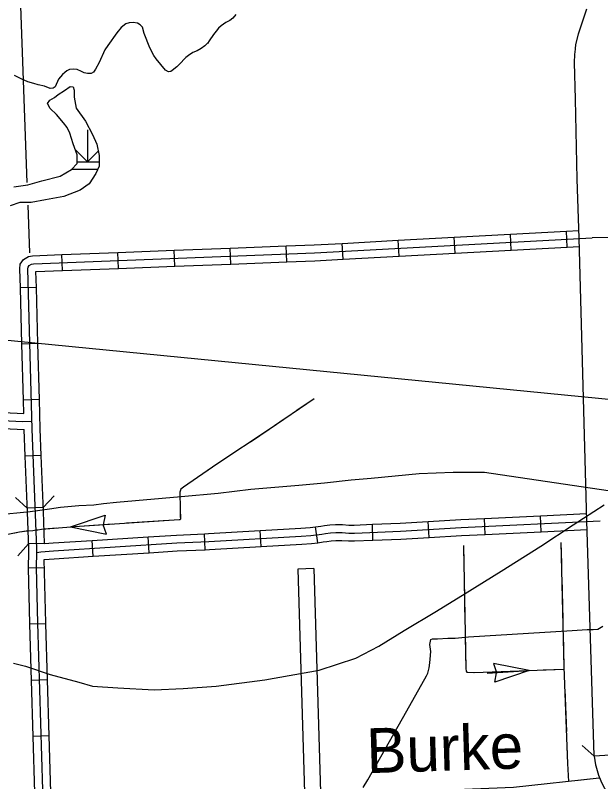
# Model space of a CAD drawing. Extents: x 1164457 to 1439835, y 1590918 to 1773502.
# Drawn here: x 1250237 to 1255743, y 1633937 to 1641151 of the extents above; entities that cross this region are included whole.
import ezdxf

# ---------------------------------------------------------------- set-up
doc = ezdxf.new("R2010")
doc.units = 0
for name, color, linetype in [('Level 10', 7, 'Continuous'), ('Level 32', 7, 'Continuous'), ('Level 35', 7, 'Continuous'), ('Level 37', 7, 'Continuous'), ('Level 38', 7, 'Continuous'), ('Level 43', 7, 'Continuous'), ('Level 44', 7, 'Continuous'), ('Level 45', 7, 'Continuous'), ('Level 46', 7, 'Continuous'), ('Level 47', 7, 'Continuous'), ('Level 5', 7, 'Continuous'), ('R_Draft', 7, 'Continuous')]:
    doc.layers.add(name, color=color, linetype=linetype)

msp = doc.modelspace()

# ---------------------------------------------------------------- linework, layer by layer
at = {"layer": 'Level 10'}
for points in [[(1255932.7, 1634192.4), (1255683.2, 1634177.2), (1255682.9, 1634182.2), (1255613.1, 1636387.6), (1255539.9, 1639052.5), (1255522.9, 1639608.2), (1255507.2, 1640362.9), (1255498.4, 1640706.4), (1255500.4, 1640783), (1255507.4, 1640833.5), (1255507.7, 1640838.1), (1255508.6, 1640872), (1255534.7, 1640977), (1255612.6, 1641210.8)], [(1255683.2, 1634177.2), (1255694, 1634093.9), (1255696.9, 1634084.6), (1255702.6, 1634062.8), (1255722, 1633998.8), (1255745.7, 1633943.1), (1255765.1, 1633903.6), (1255794.6, 1633848.4), (1255830.8, 1633799.8), (1255902, 1633727.8)]]:
    msp.add_lwpolyline(points, dxfattribs=at)
at = {"layer": 'Level 32'}
for p, q in [((1254901.8, 1638939.8), (1254893.7, 1639089.6)), ((1255429, 1638968.3), (1255421, 1639118)), ((1253847.3, 1638882.9), (1253839.3, 1639032.6)), ((1254374.6, 1638911.3), (1254366.5, 1639061.1)), ((1252263.9, 1638809.5), (1252258.2, 1638959.4)), ((1252791.6, 1638829.9), (1252785.8, 1638979.8)), ((1253320.1, 1638854.4), (1253312, 1639004.2)), ((1250681.1, 1638748.3), (1250675.3, 1638898.2)), ((1251208.7, 1638768.7), (1251202.9, 1638918.6)), ((1251736.3, 1638789.1), (1251730.5, 1638939)), ((1250435, 1638588.5), (1250285.1, 1638584.4)), ((1250449.3, 1638060.7), (1250299.4, 1638056.6)), ((1250463.6, 1637532.9), (1250313.7, 1637528.8)), ((1250480.8, 1637006), (1250330.9, 1637000.2)), ((1250499.6, 1636517.2), (1250349.7, 1636511.4)), ((1255184.2, 1636289.9), (1255177, 1636439.7)), ((1253601.7, 1636209.3), (1253595.7, 1636359.2)), ((1254130.5, 1636235.9), (1254121.5, 1636385.6)), ((1254656.8, 1636264.8), (1254649.6, 1636414.6)), ((1252550.1, 1636150.8), (1252541.2, 1636300.6)), ((1253082.5, 1636186.3), (1253062.2, 1636334.9)), ((1250969.2, 1636058.1), (1250959.6, 1636207.8)), ((1251496.2, 1636091.9), (1251486.6, 1636241.6)), ((1252021.8, 1636120.1), (1252015.3, 1636270)), ((1250512.6, 1636178.4), (1250362.7, 1636174.2)), ((1250510.2, 1635950), (1250360.3, 1635945.7)), ((1250525.3, 1635422.2), (1250375.3, 1635417.8)), ((1250540.6, 1634894.4), (1250390.7, 1634890.1)), ((1250556, 1634366.7), (1250406.1, 1634362.3))]:
    msp.add_line(p, q, dxfattribs=at)
for points in [[(1254366.5, 1639061.1), (1254893.7, 1639089.6)], [(1254893.7, 1639089.6), (1255421, 1639118)], [(1255421, 1639118), (1255537.7, 1639124.3)], [(1250677.8, 1633448.7), (1250635.7, 1633447.2), (1250602.5, 1633447.1), (1250576.8, 1633446.5), (1250550.1, 1633454), (1250529.4, 1633468.9), (1250517.9, 1633483.1), (1250509.4, 1633507.1), (1250504.9, 1633547.6), (1250450, 1635429.3), (1250435.1, 1635952.5), (1250438.3, 1636092.9), (1250439.4, 1636131.4), (1250396.1, 1637254.8), (1250355.3, 1638763.1), (1250356.9, 1638781), (1250367.4, 1638795.8), (1250389.3, 1638809.2), (1250408.7, 1638812.8), (1253052.7, 1638915.1), (1255664.9, 1639056.1)], [(1253312, 1639004.2), (1253839.3, 1639032.6)], [(1253839.3, 1639032.6), (1254366.5, 1639061.1)], [(1251730.5, 1638939), (1252258.2, 1638959.4)], [(1252258.2, 1638959.4), (1252785.8, 1638979.8)], [(1252785.8, 1638979.8), (1253049.2, 1638990), (1253312, 1639004.2)], [(1254901.8, 1638939.8), (1255429, 1638968.3)], [(1255429, 1638968.3), (1255542.1, 1638974.4)], [(1250285.1, 1638584.4), (1250280.2, 1638765.4), (1250284, 1638807.9), (1250315.2, 1638851.8), (1250361.9, 1638880.4), (1250400.3, 1638887.6), (1250675.3, 1638898.2)], [(1250675.3, 1638898.2), (1251202.9, 1638918.6)], [(1251202.9, 1638918.6), (1251730.5, 1638939)], [(1253320.1, 1638854.4), (1253847.3, 1638882.9)], [(1253847.3, 1638882.9), (1254374.6, 1638911.3)], [(1254374.6, 1638911.3), (1254901.8, 1638939.8)], [(1251736.3, 1638789.1), (1252263.9, 1638809.5)], [(1252263.9, 1638809.5), (1252791.6, 1638829.9)], [(1252791.6, 1638829.9), (1253056.2, 1638840.1), (1253320.1, 1638854.4)], [(1250435, 1638588.5), (1250431, 1638738.6), (1250681.1, 1638748.3)], [(1250681.1, 1638748.3), (1251208.7, 1638768.7)], [(1251208.7, 1638768.7), (1251736.3, 1638789.1)], [(1250299.4, 1638056.6), (1250285.1, 1638584.4)], [(1250449.3, 1638060.7), (1250435, 1638588.5)], [(1250313.7, 1637528.8), (1250299.4, 1638056.6)], [(1250463.6, 1637532.9), (1250449.3, 1638060.7)], [(1249392, 1637589.4), (1249437.9, 1637574.3), (1249498.4, 1637548.6), (1249647.2, 1637466.2), (1249695.2, 1637437.2), (1249780.8, 1637384.9), (1249817, 1637365.5), (1249849.6, 1637351.9), (1249869.3, 1637348.9), (1249928.1, 1637346.8), (1250305.7, 1637328.4), (1250394.9, 1637329.8)], [(1250317.1, 1637402.9), (1250313.7, 1637528.8)], [(1250480.8, 1637006), (1250471.1, 1637257.3), (1250463.6, 1637532.9)], [(1249872.2, 1637424.3), (1249876.4, 1637423.6), (1249931.2, 1637421.7), (1250317.1, 1637402.9)], [(1249848.9, 1637276.1), (1249862.1, 1637274.1), (1249924.9, 1637271.8), (1250321.2, 1637252.5)], [(1250330.9, 1637000.2), (1250321.2, 1637252.5)], [(1250351.2, 1636472.6), (1250330.9, 1637000.2)], [(1250501.1, 1636478.4), (1250480.8, 1637006)], [(1249739.7, 1636415.7), (1250377.2, 1636479.2), (1250557.3, 1636505), (1250663.2, 1636522.1), (1250836, 1636536.8), (1250975, 1636541.9), (1251067.7, 1636554.2), (1251190.5, 1636568.1), (1251796.5, 1636622), (1252146, 1636651.2), (1252451.2, 1636688.7), (1252903.8, 1636726.4), (1253144.6, 1636750.3), (1253395.2, 1636777.2), (1253583.4, 1636793.4), (1254036.9, 1636839.1)], [(1254036.9, 1636839.1), (1254355.4, 1636851.4), (1254649.4, 1636851.4), (1255813.8, 1636676.6)], [(1250360.3, 1635945.7), (1250360.1, 1635952.2), (1250363.3, 1636094.8), (1250364.3, 1636131.1), (1250351.2, 1636472.6)], [(1250512.6, 1636178.4), (1250501.1, 1636478.4)], [(1254649.6, 1636414.6), (1255177, 1636439.7)], [(1255177, 1636439.7), (1255611.1, 1636460.4)], [(1250438.3, 1636092.9), (1250476.8, 1636100.6), (1250596.9, 1636109.4), (1251756.2, 1636183.8), (1252059, 1636196.8), (1252926.7, 1636248.3), (1253017.2, 1636253.1), (1253121.9, 1636267.4), (1253156.3, 1636273.2), (1253202.2, 1636278.9), (1253251, 1636281.8), (1253312.6, 1636281.8), (1253372.9, 1636277.5), (1253427.4, 1636277.5), (1253860.5, 1636294.7), (1254430.9, 1636329.1), (1255738.1, 1636391.3)], [(1253062.2, 1636334.9), (1253110.6, 1636341.6), (1253145.5, 1636347.4), (1253195.3, 1636353.6), (1253248.8, 1636356.8), (1253315.3, 1636356.8), (1253375.5, 1636352.5), (1253425.9, 1636352.5), (1253595.7, 1636359.2)], [(1253595.7, 1636359.2), (1253856.7, 1636369.6), (1254121.5, 1636385.6)], [(1254121.5, 1636385.6), (1254426.9, 1636404), (1254649.6, 1636414.6)], [(1252015.3, 1636270), (1252055.1, 1636271.7), (1252541.2, 1636300.6)], [(1252541.2, 1636300.6), (1252922.5, 1636323.2), (1253010.1, 1636327.8), (1253062.2, 1636334.9)], [(1254656.8, 1636264.8), (1255184.2, 1636289.9)], [(1255184.2, 1636289.9), (1255615.6, 1636310.4)], [(1250512.6, 1636178.4), (1250591.8, 1636184.2), (1250959.6, 1636207.8)], [(1250959.6, 1636207.8), (1251486.6, 1636241.6)], [(1251486.6, 1636241.6), (1251752.2, 1636258.7), (1252015.3, 1636270)], [(1253082.5, 1636186.3), (1253133.2, 1636193.3), (1253167.1, 1636198.9), (1253209.1, 1636204.2), (1253253.2, 1636206.8), (1253310, 1636206.8), (1253370.2, 1636202.5), (1253428.9, 1636202.5), (1253601.7, 1636209.3)], [(1253601.7, 1636209.3), (1253864.2, 1636219.8), (1254130.5, 1636235.9)], [(1254130.5, 1636235.9), (1254435, 1636254.2), (1254656.8, 1636264.8)], [(1252021.8, 1636120.1), (1252062.8, 1636121.9), (1252550.1, 1636150.8)], [(1252550.1, 1636150.8), (1252930.9, 1636173.4), (1253024.3, 1636178.4), (1253082.5, 1636186.3)], [(1250969.2, 1636058.1), (1251496.2, 1636091.9)], [(1251496.2, 1636091.9), (1251760.3, 1636108.9), (1252021.8, 1636120.1)], [(1250508, 1636027.7), (1250602.1, 1636034.6), (1250969.2, 1636058.1)], [(1250525.3, 1635422.2), (1250525, 1635431.4), (1250508, 1636027.7)], [(1250375.3, 1635417.9), (1250375, 1635427.1), (1250360.3, 1635945.7)], [(1250390.7, 1634890.1), (1250375.3, 1635417.8)], [(1250540.6, 1634894.4), (1250525.3, 1635422.2)], [(1250406.1, 1634362.3), (1250390.7, 1634890.1)], [(1250556, 1634366.7), (1250540.6, 1634894.4)], [(1250421.5, 1633834.5), (1250406.1, 1634362.3)], [(1250571.4, 1633838.9), (1250556, 1634366.7)]]:
    msp.add_lwpolyline(points, dxfattribs=at)
at = {"layer": 'Level 35'}
for points in [[(1252310.8, 1641157.3), (1252282.3, 1641123.3), (1252253.8, 1641101.4), (1252217.7, 1641082.7), (1252174.9, 1641053.1), (1252147.1, 1641029), (1252127.4, 1641002.7), (1252101, 1640969.8), (1252061.9, 1640911.6), (1252046, 1640884.8)], [(1252046.5, 1640887.5), (1252018.8, 1640862.3), (1251987, 1640839.2), (1251948.6, 1640817.3), (1251908.4, 1640800.3), (1251867.5, 1640772.3), (1251842.3, 1640753.7), (1251823.7, 1640735), (1251796.9, 1640705.4), (1251779.8, 1640687.9), (1251757.9, 1640664.8), (1251712.9, 1640630.8), (1251698.7, 1640621), (1251678.5, 1640618.9), (1251651.3, 1640633), (1251561.2, 1640740.6), (1251540.3, 1640772.4), (1251502, 1640843.7), (1251449.3, 1640979.7), (1251432.9, 1641037.9), (1251412.1, 1641060.9), (1251385.7, 1641076.3), (1251346.3, 1641082.8), (1251307.9, 1641080.6), (1251276.1, 1641069.7), (1251234.4, 1641035.7), (1251191.7, 1640985.2), (1251107.2, 1640866.8), (1251078.7, 1640827.3), (1251027.2, 1640707.7), (1250991, 1640645.2), (1250971.3, 1640615.6), (1250949.4, 1640603.5), (1250947.2, 1640603.5), (1250915.4, 1640603.5), (1250883.6, 1640609), (1250860.5, 1640622.2), (1250818.9, 1640640.8), (1250780.5, 1640643), (1250746.5, 1640639.7), (1250722.4, 1640626.6), (1250701.6, 1640611.2), (1250680.7, 1640594.7), (1250644.1, 1640550.9), (1250613.1, 1640478.4), (1250593.9, 1640465.1), (1250565.8, 1640462.1), (1250512.6, 1640482.9), (1250452, 1640496.2), (1250412, 1640509.5), (1250355.9, 1640525.7), (1250292.3, 1640552.4), (1250228.9, 1640585.1)]]:
    msp.add_lwpolyline(points, dxfattribs=at)
at = {"layer": 'Level 37'}
msp.add_lwpolyline([(1255683.2, 1634177.2), (1255570.8, 1634276.6)], dxfattribs=at)
at = {"layer": 'Level 38'}
for points in [[(1250349.7, 1636511.4), (1250239.6, 1636613.3)], [(1250601.5, 1636627.2), (1250499.6, 1636517.2)], [(1250260.8, 1636064.1), (1250362.7, 1636174.2)], [(1250512.6, 1636179.9), (1250512.6, 1636179.9)]]:
    msp.add_lwpolyline(points, dxfattribs=at)
at = {"layer": 'Level 43'}
for p, q in [((1250757.1, 1636334.6), (1251082.2, 1636444.7)), ((1251082.2, 1636444.7), (1251064.3, 1636355.1)), ((1251093.7, 1636267.5), (1251064.4, 1636353.9)), ((1250757.1, 1636334.6), (1251093.7, 1636267.5)), ((1254734.4, 1635049.9), (1254763.5, 1634963.4)), ((1255071.3, 1634984.5), (1254734.4, 1635049.9)), ((1255071.3, 1634984.5), (1254746.8, 1634872.7)), ((1254746.8, 1634872.7), (1254764.9, 1634962.3))]:
    msp.add_line(p, q, dxfattribs=at)
for points in [[(1253049.3, 1637540.8), (1252624.7, 1637251.2), (1252131.4, 1636924.1), (1251818, 1636708.5)], [(1253049.3, 1637540.8), (1252885.7, 1637429.2)], [(1252776.7, 1637354.8), (1252624.7, 1637251.2), (1252448, 1637134)], [(1252338, 1637061.1), (1252131.4, 1636924.1), (1252009.4, 1636840.1)], [(1251818, 1636708.5), (1251795.7, 1636689.3), (1251785.1, 1636661), (1251789, 1636505.1), (1251789.5, 1636406.8), (1251786, 1636401), (1251777.4, 1636400.8), (1250840.7, 1636340.1), (1250482.6, 1636310), (1250449.7, 1636304.1), (1250434.8, 1636303.5), (1250400.8, 1636299.5), (1250349, 1636296.3), (1250276.5, 1636286), (1250055.4, 1636240.7), (1249996.1, 1636241.1), (1249969.4, 1636254), (1249932, 1636251.8), (1249896.5, 1636233.9), (1249828, 1636212.5)], [(1251900.6, 1636765.3), (1251818, 1636708.5), (1251795.7, 1636689.3), (1251785.1, 1636661), (1251789, 1636505.1), (1251789.4, 1636425)], [(1250219.2, 1635051.4), (1250333.1, 1635022.9), (1250565.7, 1634946.9), (1250834.6, 1634872.2), (1250962.5, 1634836.4), (1251203.1, 1634819.9), (1251544.4, 1634802), (1251817.6, 1634813.3), (1252127.2, 1634835.6), (1252585.7, 1634895.8), (1253096.7, 1634987.7), (1253440.4, 1635098.2), (1253657.2, 1635211.7), (1253896.3, 1635359.4), (1254197.8, 1635542.3), (1254469.8, 1635707.7), (1254807.2, 1635918.5), (1255180.5, 1636153.9), (1255484.8, 1636353.7), (1255776.1, 1636543.1)], [(1251152.3, 1636360.3), (1250840.7, 1636340.1), (1250757.2, 1636333.1)], [(1251679.2, 1636394.5), (1251284, 1636368.8)], [(1250357.9, 1636297.5), (1250276.5, 1636286), (1250232.7, 1636277.1)], [(1250625.7, 1636322), (1250507.5, 1636312.1)], [(1254451.8, 1636158.8), (1254473.8, 1635002), (1254476.9, 1634977.1), (1254483.1, 1634967.8), (1254553.1, 1634964.7), (1255399.2, 1634997.1)], [(1254451.8, 1636158.8), (1254455.6, 1635960.9)], [(1255368.3, 1636189.1), (1255398.4, 1635019.2), (1255428.7, 1634184.9), (1255432.6, 1634108.6), (1255441.8, 1633938.9)], [(1255368.3, 1636189.1), (1255373.4, 1635991.2)], [(1255376.8, 1635859.2), (1255387, 1635463.4)], [(1254458.1, 1635828.9), (1254465.6, 1635433)], [(1253510.4, 1633881.2), (1253552.5, 1633953.2), (1253921.5, 1634602.8), (1254105.7, 1634931.8), (1254117.4, 1634958.2), (1254131, 1635008.2), (1254136.9, 1635053.9), (1254139.1, 1635091.1), (1254144.5, 1635161.9), (1254137.2, 1635229.4), (1254147.3, 1635274.7), (1254162.5, 1635281.3), (1254177.8, 1635280.4), (1254210, 1635280.4), (1254305.2, 1635288.2), (1254373.4, 1635287.4), (1254500.7, 1635298.7), (1255474.4, 1635360.1), (1255616.9, 1635370.1), (1255672.7, 1635368), (1255717.7, 1635372.4), (1255764.8, 1635401)], [(1254468.1, 1635301), (1254473.8, 1635002), (1254476.9, 1634977.1), (1254483.1, 1634967.8), (1254543.7, 1634965.1)], [(1255390.4, 1635331.4), (1255398.4, 1635019.2), (1255401.5, 1634935.6)], [(1254676.1, 1634959.6), (1255071.3, 1634984.5)], [(1255203.2, 1634989.6), (1255399.2, 1634997.1)], [(1255406.2, 1634803.7), (1255420.6, 1634407.9)], [(1255425.4, 1634276), (1255428.7, 1634184.9), (1255432.6, 1634108.6), (1255441.8, 1633938.9)], [(1255729.5, 1633970.1), (1254922.5, 1633882.5), (1253770.1, 1633835.4), (1253586.6, 1633829.2), (1253562, 1633829.3), (1253529.6, 1633823), (1253482.5, 1633800.7), (1253450.7, 1633784.4), (1253212.2, 1633499.6)], [(1255729.5, 1633970.1), (1255532.7, 1633948.7)]]:
    msp.add_lwpolyline(points, dxfattribs=at)
at = {"layer": 'Level 44'}
for p, q in [((1250915.6, 1640071.9), (1250915.6, 1639771.9)), ((1250915.6, 1639771.9), (1250802.1, 1639885.5)), ((1250915.6, 1639771.9), (1251017.2, 1639873.5)), ((1250818.3, 1639771.9), (1251025.3, 1639771.9)), ((1250769.5, 1639703.7), (1251013.7, 1639703.7))]:
    msp.add_line(p, q, dxfattribs=at)
at = {"layer": 'Level 45'}
msp.add_lwpolyline([(1266436, 1639374.4), (1266328.5, 1639399.5), (1266286.6, 1639404.8), (1266198.6, 1639405), (1262928.8, 1639280.3), (1261020.5, 1639218.3), (1259833.6, 1639173.7), (1258803.4, 1639143.1), (1258639.6, 1639142), (1258547.8, 1639142), (1258508.3, 1639143.1), (1258467.6, 1639145.4), (1258415.4, 1639157.1), (1258375.3, 1639167.5), (1258349.1, 1639168.7), (1258324.2, 1639167.5), (1258291.6, 1639162.9), (1258189.4, 1639155.7), (1257406.3, 1639120.8), (1255939.8, 1639059.6), (1255664.9, 1639056.1)], dxfattribs=at)
at = {"layer": 'Level 46'}
for points in [[(1253043.7, 1635942.9), (1252893.8, 1635938.5), (1252956.6, 1633836.2), (1252958, 1633625.9)], [(1253043.7, 1635942.9), (1253106.6, 1633838.9), (1253108, 1633628.6)]]:
    msp.add_lwpolyline(points, dxfattribs=at)
at = {"layer": 'Level 47'}
for points in [[(1250354.1, 1639554.1), (1250487.1, 1639592.5), (1250658.6, 1639636.9), (1250765.1, 1639699), (1250818.3, 1639755.2), (1250818.3, 1639838), (1250782.8, 1639941.6), (1250750.6, 1640040.6), (1250723.7, 1640095.4), (1250691.2, 1640139.7), (1250623.2, 1640216.6), (1250564, 1640272.8), (1250540.4, 1640320.2), (1250561.1, 1640352.7), (1250605.4, 1640376.4), (1250640.9, 1640405.9), (1250700, 1640444.4), (1250753.3, 1640479.9), (1250779.9, 1640476.9), (1250791.7, 1640447.4), (1250791.7, 1640379.3), (1250809.4, 1640275.8), (1250898.1, 1640154.5), (1250963.2, 1640027.3), (1251004.6, 1639938.6), (1251025.3, 1639832.1), (1251025.3, 1639731.6), (1250995.7, 1639660.6), (1250930.7, 1639565.9), (1250847.9, 1639503.8), (1250694.1, 1639444.6), (1250522.6, 1639415.1), (1250386.6, 1639388.4)], [(1250224, 1639536.3), (1250354.1, 1639554.1)], [(1250386.6, 1639388.4), (1250280.2, 1639388.4), (1250188.5, 1639355.9)]]:
    msp.add_lwpolyline(points, dxfattribs=at)
at = {"layer": 'Level 5'}
for points in [[(1250276.8, 1641503.1), (1250345.9, 1639576.8)], [(1250353.6, 1639363), (1250369.7, 1638915.5)]]:
    msp.add_lwpolyline(points, dxfattribs=at)
at = {"layer": 'R_Draft'}
msp.add_line((1283713.8, 1634794.1), (1223029.8, 1640753.2), dxfattribs=at)

# ---------------------------------------------------------------- texts
at = {"layer": 'Level 43'}
msp.add_text('Burke', height=422, rotation=1.80229, dxfattribs=at).set_placement((1253545.8, 1634016.1))

doc.saveas('drawing.dxf')
